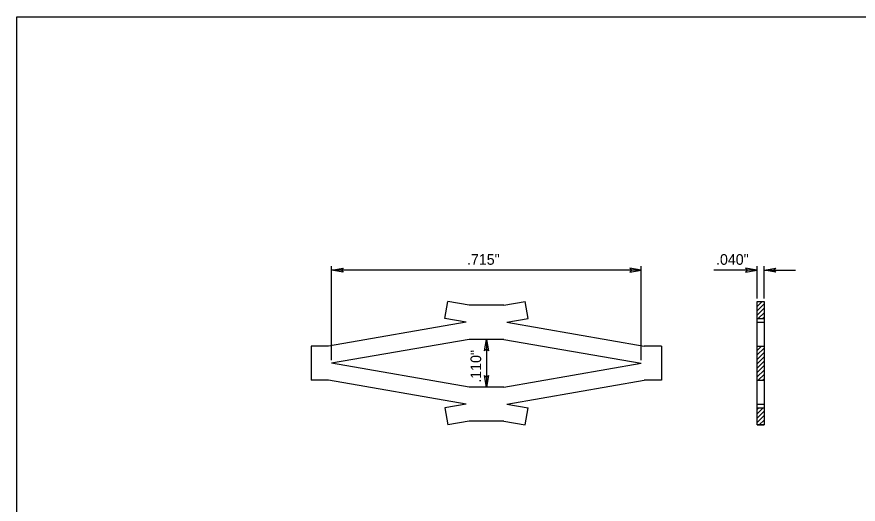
# Model space of a CAD drawing. Extents: x 99968 to 128667, y 90163 to 102182.
# Drawn here: x 99968 to 100917, y 95122 to 95672 of the extents above; entities that cross this region are included whole.
import ezdxf

# ---------------------------------------------------------------- set-up
doc = ezdxf.new("R2010")
doc.units = 0
doc.layers.add('Default', color=7, linetype='Continuous')
doc.layers.add('RD Standard Plans Active', color=7, linetype='Continuous')

msp = doc.modelspace()

# ---------------------------------------------------------------- linework, layer by layer
at = {"layer": 'Default'}
msp.add_lwpolyline([(99967.52, 95671.53), (103167.2, 95671.53), (103167.2, 93471.93), (99967.52, 93471.93)], close=True, dxfattribs=at)
at = {"layer": 'RD Standard Plans Active'}
for p, q in [((100322.89, 95284.15), (100322.89, 95390.31)), ((100672.5, 95385.74), (100322.89, 95385.74)), ((100672.5, 95284.15), (100672.5, 95390.35)), ((100803.34, 95385.74), (100754.33, 95385.74)), ((100803.34, 95353.76), (100803.34, 95390.35)), ((100811.17, 95353.76), (100811.17, 95390.35)), ((100811.17, 95385.74), (100846.48, 95385.74)), ((100450.71, 95330.98), (100454.05, 95350.25)), ((100478.14, 95346.08), (100454.05, 95350.25)), ((100497.7, 95346.08), (100478.14, 95346.08)), ((100517.26, 95346.08), (100497.7, 95346.08)), ((100517.26, 95346.08), (100541.35, 95350.25)), ((100544.68, 95330.98), (100541.35, 95350.25)), ((100803.34, 95211.03), (100803.34, 95350.25)), ((100803.34, 95344.77), (100808.83, 95350.25)), ((100803.34, 95349.73), (100803.86, 95350.25)), ((100803.34, 95339.8), (100811.17, 95347.63)), ((100803.34, 95334.84), (100811.17, 95342.67)), ((100804.44, 95330.98), (100811.17, 95337.7)), ((100474.8, 95326.81), (100319.56, 95299.91)), ((100474.8, 95326.81), (100450.71, 95330.98)), ((100520.6, 95326.81), (100544.68, 95330.98)), ((100520.6, 95326.81), (100675.84, 95299.91)), ((100803.34, 95330.98), (100811.17, 95330.98)), ((100803.34, 95326.81), (100811.17, 95326.81)), ((100809.4, 95330.98), (100811.17, 95332.74)), ((100478.14, 95307.53), (100322.89, 95280.64)), ((100517.26, 95307.53), (100478.14, 95307.53)), ((100497.7, 95307.53), (100497.7, 95253.75)), ((100517.26, 95307.53), (100672.5, 95280.64)), ((100319.56, 95299.91), (100300, 95299.91)), ((100300, 95299.91), (100300, 95261.37)), ((100695.4, 95299.91), (100675.84, 95299.91)), ((100695.4, 95299.91), (100695.4, 95261.37)), ((100803.34, 95299.91), (100811.17, 95299.91)), ((100803.34, 95294.92), (100808.34, 95299.91)), ((100803.34, 95299.88), (100803.37, 95299.91)), ((100803.34, 95289.96), (100811.17, 95297.78)), ((100803.34, 95285), (100811.17, 95292.82)), ((100803.34, 95280.03), (100811.17, 95287.86)), ((100478.14, 95253.75), (100322.89, 95280.64)), ((100517.26, 95253.75), (100672.5, 95280.64)), ((100803.34, 95275.07), (100811.17, 95282.89)), ((100803.34, 95270.11), (100811.17, 95277.93)), ((100803.34, 95265.15), (100811.17, 95272.97)), ((100804.53, 95261.37), (100811.17, 95268.01)), ((100319.56, 95261.37), (100300, 95261.37)), ((100474.8, 95234.48), (100319.56, 95261.37)), ((100520.6, 95234.48), (100675.84, 95261.37)), ((100695.4, 95261.37), (100675.84, 95261.37)), ((100803.34, 95261.37), (100811.17, 95261.37)), ((100809.49, 95261.37), (100811.17, 95263.05)), ((100517.26, 95253.75), (100478.14, 95253.75)), ((100474.8, 95234.48), (100450.71, 95230.3)), ((100450.71, 95230.3), (100454.05, 95211.03)), ((100520.6, 95234.48), (100544.68, 95230.3)), ((100541.35, 95211.03), (100544.68, 95230.3)), ((100803.34, 95234.48), (100811.17, 95234.48)), ((100803.34, 95230.3), (100811.17, 95230.3)), ((100803.34, 95223.59), (100810.06, 95230.3)), ((100803.34, 95228.55), (100805.09, 95230.3)), ((100803.34, 95218.63), (100811.17, 95226.45)), ((100803.34, 95213.67), (100811.17, 95221.49)), ((100478.14, 95215.21), (100454.05, 95211.03)), ((100497.7, 95215.21), (100478.14, 95215.21)), ((100517.26, 95215.21), (100497.7, 95215.21)), ((100517.26, 95215.21), (100541.35, 95211.03)), ((100803.34, 95211.03), (100811.17, 95211.03)), ((100805.67, 95211.03), (100811.17, 95216.53)), ((100810.63, 95211.03), (100811.17, 95211.57))]:
    msp.add_line(p, q, dxfattribs=at)
for points in [[(100335.97, 95383.52), (100322.89, 95385.74), (100335.97, 95387.96), (100333.92, 95385.74)], [(100659.43, 95383.52), (100672.5, 95385.74), (100659.43, 95387.96), (100661.48, 95385.74)], [(100790.27, 95383.52), (100803.34, 95385.74), (100790.27, 95387.96), (100792.32, 95385.74)], [(100824.24, 95383.52), (100811.17, 95385.74), (100824.24, 95387.96), (100822.19, 95385.74)], [(100495.48, 95294.46), (100497.7, 95307.53), (100499.92, 95294.46), (100497.7, 95296.51)], [(100499.92, 95266.82), (100497.7, 95253.75), (100495.48, 95266.82), (100497.7, 95264.77)]]:
    msp.add_lwpolyline(points, close=True, dxfattribs=at)
msp.add_lwpolyline([(100803.34, 95350.25), (100811.17, 95350.25), (100811.17, 95211.03), (100803.34, 95211.03)], dxfattribs=at)

# ---------------------------------------------------------------- texts
for s, p in [('.715"', (100475.71, 95391.74)), ('.040"', (100756.85, 95391.74))]:
    msp.add_text(s, height=12, dxfattribs=at).set_placement(p)
msp.add_text('.110"', height=12, rotation=90, dxfattribs=at).set_placement((100491.7, 95258.65))

doc.saveas('drawing.dxf')
